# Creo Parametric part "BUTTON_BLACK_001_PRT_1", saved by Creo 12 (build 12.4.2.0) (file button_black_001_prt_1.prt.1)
Units: Custom; MM, KILOGRAM, SECS

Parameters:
  PTC_WM_ITERATION = "0"
  PTC_WM_VERSION = "-.0"
  PTC_WM_LIFECYCLE_STATE = "In Work"
  PTC_WM_LIFECYCLE = "MO_CADDocument"
  PTC_WM_CREATED_BY = "Maximilian Roepper (Z0017RMS: MO)"
  PTC_WM_CREATED_ON = "18-Sep-26 11:36:42 AM"
  PTC_WM_MODIFIED_BY = "Maximilian Roepper (Z0017RMS: MO)"
  PTC_WM_MODIFIED_ON = "18-Sep-26 11:36:46 AM"
  PDMLINKNUMBER = "PDM000071455322"
  PTC_WM_NAME = "button_black_001_prt_1.prt"
  PTC_WM_NUMBER = "PDM000071455322"

Other parameters: WEIGHT, WEIGHT_FACTOR, WEIGHT_ADD, _MASS_TEMP, _DIFF_TEMP, MC_ERRORS, SUPPLIER

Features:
  1. coordinate system
  2. datum plane "PRT_YZ"
  3. datum plane "PRT_XY"
  4. datum plane "PRT_XZ"
  5. coordinate system
  6. datum axis
  7. datum axis
  8. datum axis
  9. coordinate system
  10. imported feature
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
Other named items: PRT, SIEMENS_MO, DRW_VIEW_ORG, PRT_X, PRT_Y, PRT_Z, CS0, ROUGH_GROB

Layers: 00_STD_CSYS-KSYS, 01_STD_PLANES-EBENEN, 02_STD_AXES-ACHSEN, 03_STD_CSYS-KSYS, 24_IMPORT_FEAT-IMPORT_KE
